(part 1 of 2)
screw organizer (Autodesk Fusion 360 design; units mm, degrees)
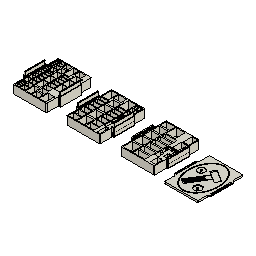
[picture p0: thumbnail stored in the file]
sketch "Sketch1" plane through (0, 0, 0) normal (0, 0, 1) x axis (1, 0, 0)
  line L1 (84.5, 75) -> (-100, 75)
  line L2 (84.5, -175) -> (84.5, 75)
  line L3 (-100, -175) -> (84.5, -175)
  line L4 (-100, 75) -> (-100, -175)
  line L5 (-112, -110) -> (-100, -110)
  line L6 (-112, 10) -> (-112, -110)
  line L7 (-100, 10) -> (-112, 10)
  line L8 (-100, -110) -> (-100, 10)
  line L9 (96.5, 10) -> (84.5, 10)
  line L10 (96.5, -110) -> (96.5, 10)
  line L11 (84.5, -110) -> (96.5, -110)
  line L12 (84.5, 10) -> (84.5, -110)
  line L13 (-103, 7) -> (-109, 7)
  line L14 (-103, -107) -> (-103, 7)
  line L15 (-109, -107) -> (-103, -107)
  line L16 (-109, 7) -> (-109, -107)
  line L17 (93.5, 7) -> (87.5, 7)
  line L18 (93.5, -107) -> (93.5, 7)
  line L19 (87.5, -107) -> (93.5, -107)
  line L20 (87.5, 7) -> (87.5, -107)
  point P6 (-100, -110)
  point P10 (84.5, 10)
  point P2 (-100, 75)
  point P3 (84.5, 75)
  point P5 (-100, -175)
  point P1 (0, 0)
  point P7 (-112, -110)
  point P9 (-100, 10)
  point P11 (96.5, 10)
  point P13 (84.5, -110)
  point P4 (84.5, -175)
  horizontal L1
  vertical L2
  horizontal L3
  vertical L4
  horizontal L5
  vertical L6
  horizontal L7
  vertical L8
  coincident L4 P6
  horizontal L9
  vertical L10
  horizontal L11
  vertical L12
  coincident L2 P10
  dimension "d1" distance P2 P3 = 184.5 (= "210 mm - 25.5 mm")
  dimension "d2" distance P2 P5 = 250
  dimension "d219" distance P1 L4 = 100
  dimension "d220" distance P1 L1 = 75
  dimension "d229" distance P6 P7 = 12
  dimension "d230" distance P6 P9 = 120
  dimension "d231" distance P2 L7 = 65 (= "d232")
  dimension "d232" distance P5 L5 = 65
  dimension "d233" distance P10 P11 = 12
  dimension "d234" distance P10 P13 = 120
  dimension "d235" distance P4 L11 = 65 (= "d236")
  dimension "d236" distance P3 L9 = 65
  dimension "d237" = 3
  dimension "d238" = 3
extrude "Extrude1" new body sketch "Sketch1" profile of L1 L2 L3 L4 L8 L12 along normal blind 5
sketch "Sketch2" plane through (0, 0, 5) normal (0, 0, 1) x axis (-1, 0, 0)
  line L1 (-84.5, 175) -> (100, 175)
  line L2 (-84.5, -75) -> (-84.5, 175)
  line L3 (100, -75) -> (-84.5, -75)
  line L4 (100, 175) -> (100, -75)
  line L5 (79.6, -70) -> (95, -70)
  line L6 (79.6, -65) -> (79.6, -70)
  line L7 (95, -65) -> (79.6, -65)
  line L8 (95, -70) -> (95, -65)
  line L9 (74.6, -70) -> (79.6, -70)
  line L10 (74.6, -18.3867) -> (74.6, -70)
  line L11 (79.6, -18.3867) -> (74.6, -18.3867)
  line L12 (79.6, -70) -> (79.6, -18.3867)
  line L13 (79.6, -65) -> (95, -65)
  line L14 (79.6, -62.3467) -> (79.6, -65)
  line L15 (95, -62.3467) -> (79.6, -62.3467)
  line L16 (95, -65) -> (95, -62.3467)
  curve K1
  curve K2
  curve K3
  curve K4
  curve K5
  curve K6
  curve K7
  curve K8
  line L17 (79.6, -62.3467) -> (95, -62.3467)
  line L18 (79.6, -56.3467) -> (79.6, -62.3467)
  line L19 (95, -56.3467) -> (79.6, -56.3467)
  line L20 (95, -62.3467) -> (95, -56.3467)
  line L21 (79.6, -56.3467) -> (95, -56.3467)
  line L22 (79.6, -53.6933) -> (79.6, -56.3467)
  line L23 (95, -53.6933) -> (79.6, -53.6933)
  line L24 (95, -56.3467) -> (95, -53.6933)
  curve K9
  curve K10
  curve K11
  curve K12
  line L25 (79.6, -53.6933) -> (95, -53.6933)
  line L26 (79.6, -46.6933) -> (79.6, -53.6933)
  line L27 (95, -46.6933) -> (79.6, -46.6933)
  line L28 (95, -53.6933) -> (95, -46.6933)
  line L29 (95, -46.6933) -> (79.6, -46.6933)
  line L30 (95, -44.04) -> (95, -46.6933)
  line L31 (79.6, -44.04) -> (95, -44.04)
  line L32 (79.6, -46.6933) -> (79.6, -44.04)
  curve K13
  curve K14
  curve K15
  curve K16
  line L33 (79.6, -44.04) -> (95, -44.04)
  line L34 (79.6, -36.04) -> (79.6, -44.04)
  line L35 (95, -36.04) -> (79.6, -36.04)
  line L36 (95, -44.04) -> (95, -36.04)
  curve K17
  curve K18
  curve K19
  curve K20
  line L37 (95, -36.04) -> (79.6, -36.04)
  line L38 (95, -33.3867) -> (95, -36.04)
  line L39 (79.6, -33.3867) -> (95, -33.3867)
  line L40 (79.6, -36.04) -> (79.6, -33.3867)
  line L41 (79.6, -33.3867) -> (95, -33.3867)
  line L42 (79.6, -23.3867) -> (79.6, -33.3867)
  line L43 (95, -23.3867) -> (79.6, -23.3867)
  line L44 (95, -33.3867) -> (95, -23.3867)
  curve K21
  curve K22
  curve K23
  curve K24
  line L45 (79.6, -23.3867) -> (95, -23.3867)
  line L46 (79.6, -18.3867) -> (79.6, -23.3867)
  line L47 (95, -18.3867) -> (79.6, -18.3867)
  line L48 (95, -23.3867) -> (95, -18.3867)
  line L49 (75.6, -18.3867) -> (95, -18.3867)
  line L50 (75.6, -12.9867) -> (75.6, -18.3867)
  line L51 (95, -12.9867) -> (75.6, -12.9867)
  line L52 (95, -18.3867) -> (95, -12.9867)
  line L53 (70.6, -18.3867) -> (74.6, -18.3867)
  line L54 (70.6, -23.3867) -> (70.6, -18.3867)
  line L55 (74.6, -23.3867) -> (70.6, -23.3867)
  line L56 (74.6, -18.3867) -> (74.6, -23.3867)
  line L57 (70.6, -18.3867) -> (75.6, -18.3867)
  line L58 (70.6, 122.44) -> (70.6, -18.3867)
  line L59 (75.6, 122.44) -> (70.6, 122.44)
  line L60 (75.6, -18.3867) -> (75.6, 122.44)
  curve K25
  curve K26
  curve K27
  curve K28
  line L61 (95, -12.9867) -> (75.6, -12.9867)
  line L62 (95, -10.3333) -> (95, -12.9867)
  line L63 (75.6, -10.3333) -> (95, -10.3333)
  line L64 (75.6, -12.9867) -> (75.6, -10.3333)
  line L65 (75.6, -10.3333) -> (95, -10.3333)
  line L66 (75.6, -3.9333) -> (75.6, -10.3333)
  line L67 (95, -3.9333) -> (75.6, -3.9333)
  line L68 (95, -10.3333) -> (95, -3.9333)
  curve K29
  curve K30
  curve K31
  curve K32
  curve K33
  curve K34
  curve K35
  curve K36
  line L69 (95, -3.9333) -> (75.6, -3.9333)
  line L70 (95, -1.28) -> (95, -3.9333)
  line L71 (75.6, -1.28) -> (95, -1.28)
  line L72 (75.6, -3.9333) -> (75.6, -1.28)
  line L73 (75.6, -1.28) -> (95, -1.28)
  line L74 (75.6, 8.12) -> (75.6, -1.28)
  line L75 (95, 8.12) -> (75.6, 8.12)
  line L76 (95, -1.28) -> (95, 8.12)
  line L77 (95, 8.12) -> (75.6, 8.12)
  line L78 (95, 10.7733) -> (95, 8.12)
  line L79 (75.6, 10.7733) -> (95, 10.7733)
  line L80 (75.6, 8.12) -> (75.6, 10.7733)
  curve K37
  curve K38
  curve K39
  curve K40
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  point P15 (79.6, -62.3467)
  point P8 (79.6, -70)
  point P10 (95, -65)
  point P19 (95, -56.3467)
  point P24 (79.6, -46.6933)
  point P25 (95, -46.6933)
  point P30 (79.6, -36.04)
  point P31 (95, -36.04)
  point P36 (79.6, -23.3867)
  point P37 (95, -23.3867)
  point P39 (95, -18.3867)
  point P42 (95, -12.9867)
  point P54 (95, -3.9333)
  point P58 (75.6, 8.12)
  point P59 (95, 8.12)
  point P61 (95, 10.7733)
  point P67 (75.6, 23.8267)
  point P64 (95, 21.1733)
  point P70 (95, 36.2267)
  point P76 (75.6, 53.28)
  point P77 (95, 53.28)
  point P86 (75.6, 74.9867)
  point P84 (95, 72.3333)
  point P92 (75.6, 98.04)
  point P89 (95, 95.3867)
  point P95 (75.6, 122.44)
  point P96 (95, 122.44)
  point P97 (72.1, 122.44)
  point P99 (95, 127.44)
  point P105 (95, 134.34)
  point P111 (95, 144.8933)
  point P117 (95, 156.4467)
  point P123 (95, 170)
  point P122 (72.1, 170)
  point P124 (72.1, 170)
  point P127 (74.6, -57.1)
  point P136 (74.6, -40.2)
  point P138 (74.6, -38.2)
  point P148 (70.6, -17.3)
  point P147 (70.6, -19.3)
  point P152 (70.6, 5.6)
  point P62 (75.6, 10.7733)
  point P165 (70.6, 20)
  point P167 (70.6, 24.0286)
  point P171 (70.6, 35.4286)
  point P177 (70.6, 52.8571)
  point P183 (70.6, 72.2857)
  point P185 (70.6, 76.3143)
  point P189 (70.6, 93.7143)
  point P191 (70.6, 97.7429)
  point P195 (70.6, 117.1429)
  point P101 (67.1, 170)
  point P205 (67.1, 142.5714)
  point P217 (46.7, -44.6)
  point P125 (51.7, -70)
  point P141 (47.7, -38.2)
  point P226 (42.7, -9.8)
  point P232 (42.7, -6.4289)
  point P235 (37.7, 26.9711)
  point P250 (37.7, 67.3711)
  point P260 (37.7, 112.7711)
  point P203 (39.2, 121.1714)
  point P207 (34.2, 170)
  point P221 (13.8, -70)
  point P277 (9.8, -16.6)
  point P295 (4.8, 18.4045)
  point P300 (4.8, 37.8379)
  point P308 (4.8, 59.2713)
  point P314 (4.8, 82.7047)
  point P244 (9.8, -11.4289)
  point P283 (4.8, 0.9711)
  point P320 (4.8, 108.138)
  point P243 (4.8, -11.4289)
  point P324 (1.3, 135.5714)
  point P267 (1.3, 170)
  point P273 (-18.1, -70)
  point P333 (-23.1, -40.6)
  point P336 (-23.1, -38.6)
  point P285 (-35.6, -16.4289)
  point P153 (42.7, 5.6)
  point P155 (70.6, 10.6)
  point P359 (-35.6, 37.2)
  point P365 (-35.6, 83.6)
  point P326 (-39.1, 170)
  point P7 (95, -70)
  point P11 (74.6, -70)
  point P16 (95, -62.3467)
  point P22 (95, -53.6933)
  point P28 (79.6, -44.04)
  point P27 (95, -44.04)
  point P34 (79.6, -33.3867)
  point P33 (95, -33.3867)
  point P40 (75.6, -18.3867)
  point P43 (70.6, -18.3867)
  point P46 (70.6, -18.3867)
  point P41 (75.6, -12.9867)
  point P51 (75.6, -10.3333)
  point P50 (95, -10.3333)
  point P53 (75.6, -3.9333)
  point P56 (75.6, -1.28)
  point P55 (95, -1.28)
  point P65 (75.6, 21.1733)
  point P68 (95, 23.8267)
  point P44 (70.6, -23.3867)
  point P71 (75.6, 36.2267)
  point P74 (75.6, 38.88)
  point P73 (95, 38.88)
  point P80 (75.6, 55.9333)
  point P83 (75.6, 72.3333)
  point P87 (95, 74.9867)
  point P90 (75.6, 95.3867)
  point P93 (95, 98.04)
  point P100 (67.1, 122.44)
  point P104 (72.1, 134.34)
  point P108 (72.1, 136.9933)
  point P107 (95, 136.9933)
  point P110 (72.1, 144.8933)
  point P114 (72.1, 147.5467)
  point P113 (95, 147.5467)
  point P119 (95, 159.1)
  point P128 (46.7, -70)
  point P133 (74.6, -55.1)
  point P135 (51.7, -40.2)
  point P139 (51.7, -38.2)
  point P140 (70.6, -38.2)
  point P143 (70.6, -19.3)
  point P144 (42.7, -38.2)
  point P142 (47.7, -19.3)
  point P149 (47.7, -17.3)
  point P156 (42.7, -6.4289)
  point P157 (37.7, -6.4289)
  point P159 (42.7, -1.4289)
  point P160 (37.7, 5.6)
  point P164 (42.7, 20)
  point P168 (42.7, 24.0286)
  point P174 (70.6, 39.4571)
  point P180 (70.6, 56.8857)
  point P182 (42.7, 72.2857)
  point P186 (42.7, 76.3143)
  point P188 (42.7, 93.7143)
  point P192 (42.7, 97.7429)
  point P47 (70.6, 122.44)
  point P196 (67.1, 122.44)
  point P199 (67.1, 117.1429)
  point P202 (67.1, 121.1714)
  point P206 (34.2, 121.1714)
  point P211 (67.1, 146.6)
  point P214 (67.1, 170)
  point P215 (18.8, -70)
  point P218 (18.8, -44.6)
  point P224 (14.8, -38.2)
  point P227 (9.8, -38.2)
  point P233 (9.8, -6.4289)
  point P236 (13.8, -38.2)
  point P238 (9.8, -43.2)
  point P239 (4.8, -6.4289)
  point P242 (4.8, -6.4289)
  point P247 (37.7, 28.9711)
  point P253 (37.7, 69.3711)
  point P256 (37.7, 112.7711)
  point P259 (34.2, 116.1714)
  point P262 (6.3, 170)
  point P264 (34.2, 121.6)
  point P265 (6.3, 116.1714)
  point P266 (1.3, 116.1714)
  point P271 (1.3, 111.1714)
  point P272 (9.8, -70)
  point P276 (-18.1, -11.4289)
  point P278 (-23.1, -11.4289)
  point P281 (-30.6, -11.4289)
  point P284 (-35.6, -11.4289)
  point P286 (-23.1, -16.4289)
  point P287 (-35.6, -11.4289)
  point P292 (4.8, 4.0045)
  point P298 (4.8, 21.4379)
  point P297 (-30.6, 21.4379)
  point P301 (-30.6, 37.8379)
  point P304 (-30.6, 40.8713)
  point P303 (4.8, 40.8713)
  point P307 (4.8, 59.2713)
  point P306 (-30.6, 59.2713)
  point P310 (-30.6, 62.3047)
  point P309 (4.8, 62.3047)
  point P313 (4.8, 82.7047)
  point P312 (-30.6, 82.7047)
  point P316 (-30.6, 85.738)
  point P315 (4.8, 85.738)
  point P319 (4.8, 108.138)
  point P322 (-34.1, 111.1714)
  point P325 (-39.1, 111.1714)
  point P327 (-34.1, 170)
  point P330 (-34.1, 143.6)
  point P279 (-23.1, -70)
  point P331 (-58.5, -70)
  point P337 (-63.5, -70)
  point P340 (-35.6, -38.6)
  point P341 (-71, -38.6)
  point P343 (-35.6, -4.2)
  point P344 (-76, -38.6)
  point P349 (-39.1, 106.1714)
  point P342 (-71, -4.2)
  point P352 (-71, -2.2)
  point P353 (-63.5, -40.6)
  point P356 (-63.5, -43.6)
  point P351 (-35.6, -2.2)
  point P362 (-35.6, 39.2)
  point P368 (-35.6, 85.6)
  point P369 (-74.5, 170)
  point P371 (-39.1, 120.6)
  point P372 (-74.5, 85.6)
  point P373 (-79.5, 85.6)
  horizontal L5
  vertical L6
  horizontal L7
  vertical L8
  horizontal L9
  vertical L10
  horizontal L11
  vertical L12
  horizontal L13
  vertical L14
  horizontal L15
  vertical L16
  coincident L12 P15
  coincident P8
  coincident L3
  coincident P10
  coincident L4
  horizontal L17
  vertical L18
  horizontal L19
  vertical L20
  horizontal L21
  vertical L22
  horizontal L23
  vertical L24
  coincident P19
  coincident L4
  horizontal L25
  vertical L26
  horizontal L27
  vertical L28
  coincident L12 P24
  horizontal L29
  vertical L30
  horizontal L31
  vertical L32
  coincident L4
  coincident P25
  horizontal L33
  vertical L34
  horizontal L35
  vertical L36
  coincident L12 P30
  coincident L4
  coincident P31
  horizontal L37
  vertical L38
  horizontal L39
  vertical L40
  horizontal L41
  vertical L42
  horizontal L43
  vertical L44
  coincident L12 P36
  coincident P37
  coincident L4
  horizontal L45
  vertical L46
  horizontal L47
  vertical L48
  horizontal L49
  vertical L50
  horizontal L51
  vertical L52
  horizontal L53
  vertical L54
  horizontal L55
  vertical L56
  horizontal L57
  vertical L58
  horizontal L59
  vertical L60
  coincident P36
  coincident P39
  horizontal L61
  vertical L62
  horizontal L63
  vertical L64
  horizontal L65
  vertical L66
  coincident P42
  coincident L4
  coincident P54
  coincident L4
  collinear L60 L66
  horizontal L69
  vertical L70
  horizontal L71
  vertical L72
  horizontal L73
  vertical L74
  horizontal L75
  vertical L76
  coincident L60 P58
  horizontal L77
  vertical L78
  horizontal L79
  vertical L80
  coincident P59
  coincident L4
  coincident L4
  coincident P61
  coincident L60 P67
  coincident P64
  collinear L12 L22
  collinear L12 L18
  coincident L4
  coincident P70
  coincident L60 P76
  coincident L4
  coincident P77
  coincident L60 P86
  coincident L4
  coincident P84
  coincident L60 P92
  coincident L4
  coincident P89
  coincident L60 P95
  coincident L4
  coincident P96
  coincident P97
  coincident P99
  coincident L4
  coincident P105
  coincident L4
  coincident P111
  coincident L4
  coincident P117
  coincident L4
  coincident P123
  coincident P122 P124
  coincident P8
  coincident P127
  midpoint L22
  coincident P136
  coincident L10 P138
  coincident L58 P148
  coincident L34
  coincident P147
  coincident L50
  coincident P152
  coincident P62
  coincident P165
  coincident L58 P167
  coincident P171
  coincident L60
  coincident P177
  coincident L60
  coincident P183
  coincident L58 P185
  coincident P189
  coincident L58 P191
  coincident L60
  coincident P195
  coincident P101
  coincident P205
  collinear L71 K39
  collinear L63 K35
  collinear L47 K31
  collinear L39 K23
  collinear L33 K19
  collinear L23 K15
  collinear L17 K11
  coincident P217
  coincident P125
  coincident P141
  coincident P226
  coincident P232
  coincident P235
  coincident P250
  coincident P260
  coincident P203
  coincident P207
  coincident P221
  coincident P277
  coincident P295
  coincident P300
  coincident P308
  coincident P314
  coincident P244
  coincident P283
  coincident P320
  coincident P243
  coincident P324
  coincident P267
  coincident P273
  coincident P333
  coincident P336
  coincident P285
  coincident P153
  coincident P155
  coincident P359
  coincident P365
  coincident P326
  dimension "d5" = -5
  dimension "d6" distance P7 P8 = 15.4 (= "( 3 * 5 ) * 1 mm + 0.4 mm")
  dimension "d7" distance P7 P10 = 5 (= "1.6 mm + 0.4 mm + 3 mm")
  dimension "d8" distance P8 P11 = 5
  dimension "d10" distance P10 P16 = 2.6533 (= "d73")
  dimension "d13" distance P16 P19 = 6
  dimension "d14" distance P19 P22 = 2.6533 (= "d10")
  dimension "d16" distance P22 P25 = 7
  dimension "d17" distance P24 P28 = 2.6533 (= "d14")
  dimension "d19" distance P27 P31 = 8
  dimension "d21" distance P30 P34 = 2.6533 (= "d17")
  dimension "d22" distance P33 P37 = 10
  dimension "d24" distance P39 P40 = 19.4 (= "( 3.8 * 5 ) * 1 mm + 0.4 mm")
  dimension "d25" distance P39 P42 = 5.4 (= "5 mm + 0.4 mm")
  dimension "d26" distance L50 P43 = 5
  dimension "d27" distance P40 P46 = 5 (= "d8")
  dimension "d30" distance P41 P51 = 2.6533 (= "d21")
  dimension "d31" distance P50 P54 = 6.4
  dimension "d34" distance P53 P56 = 2.6533 (= "d30")
  dimension "d35" distance P55 P59 = 9.4
  dimension "d36" distance P58 P62 = 2.6533 (= "d34")
  dimension "d38" distance P62 P65 = 10.4
  dimension "d40" distance P64 P68 = 2.6533 (= "d36")
  dimension "d41" distance P43 P44 = 5 (= "d26")
  dimension "d42" distance P67 P71 = 12.4
  dimension "d44" distance P71 P74 = 2.6533 (= "d40")
  dimension "d45" distance P73 P77 = 14.4
  dimension "d47" distance P76 P80 = 2.6533 (= "d44")
  dimension "d48" distance P80 P83 = 16.4
  dimension "d49" distance P84 P87 = 2.6533 (= "d47")
  dimension "d51" distance P86 P90 = 20.4
  dimension "d52" distance P89 P93 = 2.6533 (= "d49")
  dimension "d54" distance P93 P96 = 24.4
  dimension "d56" distance P96 P97 = 22.9 (= "( 4.5 * 5 ) * 1 mm + 0.4 mm")
  dimension "d57" distance P96 P99 = 5
  dimension "d58" distance P97 P100 = 5
  dimension "d60" distance P99 P105 = 6.9
  dimension "d61" distance P104 P108 = 2.6533 (= "d52")
  dimension "d62" distance P107 P111 = 7.9
  dimension "d65" distance P110 P114 = 2.6533 (= "d61")
  dimension "d66" distance P113 P117 = 8.9
  dimension "d69" distance P119 P123 = 10.9
  dimension "d71" distance L47 K27 = 5
  dimension "d73" distance = 2.6533
  dimension "d74" distance P11 P125 = 22.9
  dimension "d75" distance P11 P127 = 12.9
  dimension "d76" distance P125 P128 = 5
  dimension "d77" distance P127 P133 = 2
  dimension "d79" distance P133 P136 = 14.9
  dimension "d81" distance P135 P139 = 2
  dimension "d82" distance P140 P141 = 22.9
  dimension "d83" distance P140 P143 = 18.9
  dimension "d84" distance P141 P144 = 5
  dimension "d85" distance P142 P149 = 2
  dimension "d86" distance P148 P152 = 22.9
  dimension "d89" distance P152 P153 = 27.9 (= "( 5.5 * 5 ) * 1 mm + 0.4 mm")
  dimension "d90" distance P152 P155 = 5
  dimension "d91" distance P156 P157 = 5
  dimension "d92" distance P156 P159 = 5
  dimension "d93" distance P153 P160 = 5
  dimension "d95" distance P155 P165 = 9.4
  dimension "d97" distance P164 P168 = 4.0286 (= "d100")
  dimension "d98" distance P167 P171 = 11.4
  dimension "d100" distance P171 P174 = 4.0286 (= "d103")
  dimension "d101" distance P174 P177 = 13.4
  dimension "d103" distance P177 P180 = 4.0286 (= "d106")
  dimension "d104" distance P180 P183 = 15.4
  dimension "d106" distance P182 P186 = 4.0286 (= "d109")
  dimension "d107" distance P185 P189 = 17.4
  dimension "d109" distance P188 P192 = 4.0286 (= "d114")
  dimension "d110" distance P191 P195 = 19.4
  dimension "d112" distance P47 P196 = 3.5
  dimension "d114" distance P199 P202 = 4.0286 (= "d120")
  dimension "d115" distance P202 P203 = 27.9
  dimension "d116" distance P202 P205 = 21.4
  dimension "d117" distance P203 P206 = 5
  dimension "d119" distance P211 P214 = 23.4
  dimension "d120" distance = 4.0286
  dimension "d123" distance P128 P215 = 27.9
  dimension "d124" distance P128 P217 = 25.4
  dimension "d125" distance P217 P218 = 27.9
  dimension "d126" distance P215 P221 = 5
  dimension "d128" distance P144 P224 = 27.9
  dimension "d129" distance P144 P226 = 28.4
  dimension "d130" distance P224 P227 = 5
  dimension "d132" distance = 6.4
  dimension "d134" distance P157 P233 = 27.9
  dimension "d135" distance P157 P235 = 33.4
  dimension "d136" distance P227 P236 = 4
  dimension "d137" distance P227 P238 = 5
  dimension "d138" distance P233 P239 = 5
  dimension "d139" distance P233 P242 = 5
  dimension "d140" distance P233 P244 = 5
  dimension "d142" distance P235 P247 = 2
  dimension "d154" distance P247 P250 = 38.4
  dimension "d155" distance P250 P253 = 2
  dimension "d156" distance P253 P256 = 43.4
  dimension "d157" distance P206 P259 = 5
  dimension "d158" distance = 3.3711
  dimension "d159" distance P207 P262 = 27.9
  dimension "d160" distance P207 P264 = 48.4
  dimension "d161" distance P265 P266 = 5
  dimension "d162" distance P266 P271 = 5
  dimension "d166" distance P272 P273 = 27.9
  dimension "d167" distance = 53.4
  dimension "d168" distance P276 P278 = 5
  dimension "d171" distance P243 P281 = 35.4 (= "( 7 * 5 ) * 1 mm + 0.4 mm")
  dimension "d172" distance P243 P283 = 12.4
  dimension "d173" distance P278 P284 = 12.5
  dimension "d174" distance P278 P286 = 5
  dimension "d175" distance P281 P287 = 5
  dimension "d176" distance P283 P292 = 3.0334 (= "d178")
  dimension "d177" distance P292 P295 = 14.4
  dimension "d178" distance P295 P298 = 3.0334 (= "d180")
  dimension "d179" distance P297 P301 = 16.4
  dimension "d180" distance P301 P304 = 3.0334 (= "d182")
  dimension "d181" distance P303 P307 = 18.4
  dimension "d182" distance P306 P310 = 3.0334 (= "d184")
  dimension "d183" distance P309 P313 = 20.4
  dimension "d184" distance P312 P316 = 3.0334 (= "d186")
  dimension "d185" distance P315 P319 = 22.4
  dimension "d186" distance = 3.0334
  dimension "d194" distance P271 P322 = 35.4
  dimension "d195" distance P271 P324 = 24.4
  dimension "d196" distance P322 P325 = 5
  dimension "d197" distance P327 P330 = 26.4
  dimension "d200" distance P279 P331 = 35.4
  dimension "d201" distance P279 P333 = 29.4
  dimension "d202" distance P333 P336 = 2
  dimension "d203" distance P331 P337 = 5
  dimension "d204" distance P340 P341 = 35.4
  dimension "d205" distance P340 P343 = 34.4
  dimension "d206" distance P341 P344 = 5
  dimension "d207" distance P325 P349 = 5
  dimension "d208" distance P342 P352 = 2
  dimension "d211" distance P353 P356 = 3
  dimension "d212" distance P351 P359 = 39.4
  dimension "d213" distance P359 P362 = 2
  dimension "d214" distance P362 P365 = 44.4
  dimension "d215" distance P365 P368 = 2
  dimension "d216" distance P326 P369 = 35.4
  dimension "d217" distance P326 P371 = 49.4
  dimension "d218" distance P372 P373 = 5
  dimension "d11" Text1-Height = 4
  dimension "d12" Text2-Height = 4
  dimension "d15" Text3-Height = 4
  dimension "d18" Text4-Height = 4
  dimension "d20" Text5-Height = 4
  dimension "d23" Text6-Height = 4
  dimension "d29" Text7-Height = 4
  dimension "d32" Text8-Height = 4
  dimension "d33" Text9-Height = 4
  dimension "d37" Text10-Height = 4
  dimension "d39" Text11-Height = 4
  dimension "d43" Text12-Height = 4
  dimension "d46" Text13-Height = 3.5
  dimension "d50" Text14-Height = 3.5
  dimension "d53" Text15-Height = 3.5
  dimension "d55" Text16-Height = 3
  dimension "d59" Text17-Height = 4
  dimension "d63" Text18-Height = 4
  dimension "d64" Text19-Height = 4
  dimension "d67" Text20-Height = 4
  dimension "d70" Text21-Height = 4
  dimension "d78" Text22-Height = 3.5
  dimension "d80" Text23-Height = 3.5
  dimension "d87" Text24-Height = 4
  dimension "d88" Text25-Height = 3
  dimension "d96" Text27-Height = 4
  dimension "d99" Text28-Height = 4
  dimension "d102" Text29-Height = 3.5
  dimension "d105" Text30-Height = 3.5
  dimension "d108" Text31-Height = 3.5
  dimension "d111" Text32-Height = 3.5
  dimension "d121" Text33-Height = 3
  dimension "d122" Text34-Height = 3
  dimension "d127" Text35-Height = 3
  dimension "d131" Text36-Height = 3
  dimension "d141" Text37-Height = 3
  dimension "d163" Text38-Height = 3
  dimension "d164" Text39-Height = 3
  dimension "d165" Text40-Height = 3
  dimension "d169" Text41-Height = 3
  dimension "d187" Text43-Height = 3.5
  dimension "d188" Text44-Height = 3.5
  dimension "d189" Text45-Height = 3.5
  dimension "d190" Text46-Height = 3.5
  dimension "d191" Text47-Height = 4
  dimension "d192" Text48-Height = 3.5
  dimension "d193" Text48-Height = 3.5
  dimension "d198" Text49-Height = 3
  dimension "d199" Text50-Height = 3
  dimension "d209" Text51-Height = 3
  dimension "d210" Text52-Height = 4
  dimension "d223" Text52-Height = 4
  dimension "d224" Text53-Height = 3
  dimension "d225" Text54-Height = 3
  dimension "d226" Text55-Height = 3
sketch "Sketch3" plane through (0, 0, 0) normal (0, 0, 1) x axis (1, 0, 0)
  line L1 (81.4, 200) -> (50, 200)
  line L2 (81.4, 252.9) -> (81.4, 200)
  line L3 (50, 252.9) -> (81.4, 252.9)
  line L4 (50, 200) -> (50, 252.9)
  line L5 (76.4, 205) -> (55, 205)
  line L6 (76.4, 247.9) -> (76.4, 205)
  line L7 (55, 247.9) -> (76.4, 247.9)
  line L8 (55, 205) -> (55, 247.9)
  point P2 (50, 200)
  point P3 (81.4, 200)
  point P5 (50, 252.9)
  point P6 (55, 205)
  point P7 (76.4, 205)
  point P9 (55, 247.9)
  horizontal L1
  vertical L2
  horizontal L3
  vertical L4
  horizontal L5
  vertical L6
  horizontal L7
  vertical L8
  dimension "d143" distance P2 P3 = 31.4 (= "21.4 mm + 10 mm")
  dimension "d144" distance P2 P5 = 52.9 (= "( 8.5 * 5 ) * 1 mm + 0.4 mm + 10 mm")
  dimension "d145" distance P6 P7 = 21.4
  dimension "d146" distance P6 P9 = 42.9
  dimension "d147" distance L1 L5 = 5
  dimension "d148" distance L4 L8 = 5
  dimension "d149" distance L2 L6 = 5
extrude "Extrude2" new body sketch "Sketch3" against normal blind 5
extrude "Extrude3" add sketch "Sketch3" along normal blind 10
extrude "Extrude4" add sketch "Sketch2" along normal blind 40
extrude "Extrude5" cut sketch "Sketch2" along normal blind 44
extrude "Extrude6" add sketch "Sketch1" profile of L2 L4 L5 L6 L7 L8 L9 L10 L11 L12 L16 L13 L15 L14 L20 L17 L18 L19 along normal blind 50
extrude "Extrude7" add sketch "Sketch1" profile of L16 L13 L15 L14 L20 L17 L18 L19 along normal blind 70
fillet "Fillet1" radius 3
extrude "Extrude8" add sketch "Sketch2" along normal blind 38
fillet "Fillet2" radius 3
sketch "Sketch4" plane through (0, 0, 0) normal (0, 0, 1) x axis (1, 0, 0)
  line L1 (382.7937, 73.3642) -> (198.2937, 73.3642)
  line L2 (382.7937, -176.6358) -> (382.7937, 73.3642)
  line L3 (198.2937, -176.6358) -> (382.7937, -176.6358)
  line L4 (198.2937, 73.3642) -> (198.2937, -176.6358)
  point P2 (198.2937, 73.3642)
  point P3 (382.7937, 73.3642)
  point P5 (198.2937, -176.6358)
  horizontal L1
  vertical L2
  horizontal L3
  vertical L4
  dimension "d249" distance P2 P3 = 184.5
  dimension "d250" distance P2 P5 = 250
extrude "Extrude9" new body sketch "Sketch4" along normal blind 5
sketch "Sketch5" plane through (0, 0, 5) normal (0, 0, 1) x axis (-1, 0, 0)
  line L1 (-382.7937, 176.6358) -> (-198.2937, 176.6358)
  line L2 (-382.7937, -73.3642) -> (-382.7937, 176.6358)
  line L3 (-198.2937, -73.3642) -> (-382.7937, -73.3642)
  line L4 (-198.2937, 176.6358) -> (-198.2937, -73.3642)
  line L5 (-377.7937, -68.3642) -> (-377.7937, 171.6358)
  line L6 (-203.2937, -68.3642) -> (-377.7937, -68.3642)
  line L7 (-203.2937, 171.6358) -> (-203.2937, -68.3642)
  line L8 (-377.7937, 171.6358) -> (-203.2937, 171.6358)
  line L9 (-238.6937, -68.3642) -> (-203.2937, -68.3642)
  line L10 (-238.6937, -13.9642) -> (-238.6937, -68.3642)
  line L11 (-203.2937, -13.9642) -> (-238.6937, -13.9642)
  line L12 (-203.2937, -68.3642) -> (-203.2937, -13.9642)
  line L13 (-243.6937, -68.3642) -> (-238.6937, -68.3642)
  line L14 (-243.6937, -13.9642) -> (-243.6937, -68.3642)
  line L15 (-238.6937, -13.9642) -> (-243.6937, -13.9642)
  line L16 (-238.6937, -68.3642) -> (-238.6937, -13.9642)
  line L17 (-246.1937, -13.9642) -> (-203.2937, -13.9642)
  line L18 (-246.1937, -8.9642) -> (-246.1937, -13.9642)
  line L19 (-203.2937, -8.9642) -> (-246.1937, -8.9642)
  line L20 (-203.2937, -13.9642) -> (-203.2937, -8.9642)
  curve K1
  curve K2
  curve K3
  curve K4
  curve K5
  curve K6
  curve K7
  curve K8
  curve K9
  curve K10
  curve K11
  curve K12
  line L21 (-251.1937, -13.9642) -> (-246.1937, -13.9642)
  line L22 (-251.1937, 171.6358) -> (-251.1937, -13.9642)
  line L23 (-246.1937, 171.6358) -> (-251.1937, 171.6358)
  line L24 (-246.1937, -13.9642) -> (-246.1937, 171.6358)
  line L25 (-251.1937, -13.9642) -> (-243.6937, -13.9642)
  line L26 (-251.1937, -18.9642) -> (-251.1937, -13.9642)
  line L27 (-243.6937, -18.9642) -> (-251.1937, -18.9642)
  line L28 (-243.6937, -13.9642) -> (-243.6937, -18.9642)
  line L29 (-246.1937, -8.9642) -> (-203.2937, -8.9642)
  line L30 (-246.1937, 6.4358) -> (-246.1937, -8.9642)
  line L31 (-203.2937, 6.4358) -> (-246.1937, 6.4358)
  line L32 (-203.2937, -8.9642) -> (-203.2937, 6.4358)
  line L33 (-246.1937, 6.4358) -> (-203.2937, 6.4358)
  line L34 (-246.1937, 11.5691) -> (-246.1937, 6.4358)
  line L35 (-203.2937, 11.5691) -> (-246.1937, 11.5691)
  line L36 (-203.2937, 6.4358) -> (-203.2937, 11.5691)
  line L37 (-246.1937, 11.5691) -> (-203.2937, 11.5691)
  line L38 (-246.1937, 28.9691) -> (-246.1937, 11.5691)
  line L39 (-203.2937, 28.9691) -> (-246.1937, 28.9691)
  line L40 (-203.2937, 11.5691) -> (-203.2937, 28.9691)
  line L41 (-246.1937, 28.9691) -> (-203.2937, 28.9691)
  line L42 (-246.1937, 34.1024) -> (-246.1937, 28.9691)
  line L43 (-203.2937, 34.1024) -> (-246.1937, 34.1024)
  line L44 (-203.2937, 28.9691) -> (-203.2937, 34.1024)
  line L45 (-246.1937, 34.1024) -> (-203.2937, 34.1024)
  line L46 (-246.1937, 53.5024) -> (-246.1937, 34.1024)
  line L47 (-203.2937, 53.5024) -> (-246.1937, 53.5024)
  line L48 (-203.2937, 34.1024) -> (-203.2937, 53.5024)
  line L49 (-246.1937, 53.5024) -> (-203.2937, 53.5024)
  line L50 (-246.1937, 58.6358) -> (-246.1937, 53.5024)
  line L51 (-203.2937, 58.6358) -> (-246.1937, 58.6358)
  line L52 (-203.2937, 53.5024) -> (-203.2937, 58.6358)
  line L53 (-246.1937, 58.6358) -> (-203.2937, 58.6358)
  line L54 (-246.1937, 80.0358) -> (-246.1937, 58.6358)
  line L55 (-203.2937, 80.0358) -> (-246.1937, 80.0358)
  line L56 (-203.2937, 58.6358) -> (-203.2937, 80.0358)
  line L57 (-246.1937, 80.0358) -> (-203.2937, 80.0358)
  line L58 (-246.1937, 85.1691) -> (-246.1937, 80.0358)
  line L59 (-203.2937, 85.1691) -> (-246.1937, 85.1691)
  line L60 (-203.2937, 80.0358) -> (-203.2937, 85.1691)
  line L61 (-246.1937, 85.1691) -> (-203.2937, 85.1691)
  line L62 (-246.1937, 108.5691) -> (-246.1937, 85.1691)
  line L63 (-203.2937, 108.5691) -> (-246.1937, 108.5691)
  line L64 (-203.2937, 85.1691) -> (-203.2937, 108.5691)
  line L65 (-246.1937, 108.5691) -> (-203.2937, 108.5691)
  line L66 (-246.1937, 113.7024) -> (-246.1937, 108.5691)
  line L67 (-203.2937, 113.7024) -> (-246.1937, 113.7024)
  line L68 (-203.2937, 108.5691) -> (-203.2937, 113.7024)
  line L69 (-246.1937, 113.7024) -> (-203.2937, 113.7024)
  line L70 (-246.1937, 139.1024) -> (-246.1937, 113.7024)
  line L71 (-203.2937, 139.1024) -> (-246.1937, 139.1024)
  line L72 (-203.2937, 113.7024) -> (-203.2937, 139.1024)
  line L73 (-246.1937, 171.6358) -> (-203.2937, 171.6358)
  line L74 (-246.1937, 144.2358) -> (-246.1937, 171.6358)
  line L75 (-203.2937, 144.2358) -> (-246.1937, 144.2358)
  line L76 (-203.2937, 171.6358) -> (-203.2937, 144.2358)
  curve K13
  curve K14
  curve K15
  curve K16
  curve K17
  curve K18
  curve K19
  curve K20
  curve K21
  curve K22
  curve K23
  curve K24
  curve K25
  curve K26
  curve K27
  curve K28
  curve K29
  curve K30
  curve K31
  curve K32
  curve K33
  curve K34
  curve K35
  curve K36
  curve K37
  curve K38
  curve K39
  curve K40
  line L77 (-286.5937, -68.3642) -> (-243.6937, -68.3642)
  line L78 (-286.5937, -37.9642) -> (-286.5937, -68.3642)
  line L79 (-243.6937, -37.9642) -> (-286.5937, -37.9642)
  line L80 (-243.6937, -68.3642) -> (-243.6937, -37.9642)
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  point P10 (-238.6937, -68.3642)
  point P12 (-203.2937, -13.9642)
  point P16 (-246.1937, -13.9642)
  point P18 (-203.2937, -8.9642)
  point P20 (-251.1937, 171.6358)
  point P26 (-246.1937, 6.4358)
  point P29 (-246.1937, 11.5691)
  point P32 (-246.1937, 28.9691)
  point P35 (-246.1937, 34.1024)
  point P38 (-246.1937, 53.5024)
  point P41 (-246.1937, 58.6358)
  point P44 (-246.1937, 80.0358)
  point P47 (-246.1937, 85.1691)
  point P50 (-246.1937, 108.5691)
  point P53 (-246.1937, 113.7024)
  point P56 (-246.1937, 139.1024)
  point P59 (-246.1937, 144.2358)
  point P27 (-203.2937, 6.4358)
  point P33 (-203.2937, 28.9691)
  point P39 (-203.2937, 53.5024)
  point P45 (-203.2937, 80.0358)
  point P51 (-203.2937, 108.5691)
  point P57 (-203.2937, 139.1024)
  point P9 (-203.2937, 171.6358)
  point P95 (-299.0937, -68.3642)
  point P106 (-344.4937, 171.6358)
  point P102 (-349.4937, -12.9642)
  point P104 (-299.0937, -7.9642)
  point P63 (-243.6937, -37.9642)
  point P73 (-251.1937, 6.9358)
  point P85 (-251.1937, 56.8358)
  point P91 (-251.1937, 111.7358)
  point P67 (-291.5937, -68.3642)
  point P98 (-299.0937, -12.9642)
  point P110 (-299.0937, 8.4358)
  point P116 (-299.0937, 30.6358)
  point P122 (-299.0937, 54.8358)
  point P128 (-299.0937, 81.0358)
  point P134 (-299.0937, 109.2358)
  point P140 (-299.0937, 139.4358)
  point P75 (-299.0937, 171.6358)
  point P144 (-198.2937, 111.6358)
  point P148 (-382.7937, 111.6358)
  point P176 (-377.7937, 22.4358)
  point P179 (-377.7937, -17.9642)
  point P99 (-346.9937, -68.3642)
  point P163 (-363.3937, -68.3642)
  point P164 (-363.3937, -46.9642)
  point P171 (-346.9937, -42.3642)
  point P195 (-377.7937, 50.0358)
  point P174 (-349.4937, 17.4358)
  point P181 (-354.8937, 22.4358)
  point P184 (-359.4437, 22.4358)
  point P175 (-377.7937, 17.4358)
  point P188 (-370.3937, 22.4358)
  point P187 (-359.4437, 40.8358)
  point P191 (-349.4937, 47.0358)
  point P190 (-377.7937, 43.8358)
  point P196 (-367.3937, 50.0358)
  point P199 (-349.4937, 80.6358)
  point P204 (-361.3937, 123.2358)
  point P206 (-377.7937, -40.9142)
  point P8 (-203.2937, -68.3642)
  point P13 (-243.6937, -68.3642)
  point P15 (-238.6937, -13.9642)
  point P19 (-251.1937, -13.9642)
  point P14 (-243.6937, -13.9642)
  point P24 (-243.6937, -18.9642)
  point P30 (-203.2937, 11.5691)
  point P36 (-203.2937, 34.1024)
  point P42 (-203.2937, 58.6358)
  point P48 (-203.2937, 85.1691)
  point P54 (-203.2937, 113.7024)
  point P60 (-203.2937, 144.2358)
  point P61 (-286.5937, -68.3642)
  point P66 (-243.6937, -28.4642)
  point P69 (-286.5937, -35.9642)
  point P70 (-251.1937, -28.4642)
  point P71 (-294.0937, -28.4642)
  point P74 (-299.0937, -28.4642)
  point P79 (-299.0937, -33.4642)
  point P82 (-251.1937, 16.4358)
  point P88 (-251.1937, 66.3358)
  point P94 (-251.1937, 121.2358)
  point P96 (-341.9937, -68.3642)
  point P101 (-341.9937, -12.9642)
  point P105 (-344.4937, -12.9642)
  point P113 (-299.0937, 12.2358)
  point P119 (-299.0937, 34.4358)
  point P125 (-299.0937, 58.6358)
  point P131 (-299.0937, 84.8358)
  point P137 (-299.0937, 113.0358)
  point P143 (-299.0937, 143.2358)
  point P145 (-186.2937, 111.6358)
  point P147 (-198.2937, -8.3642)
  point P149 (-394.7937, 111.6358)
  point P151 (-382.7937, -8.3642)
  point P160 (-357.3937, -68.3642)
  point P162 (-346.9937, -52.9642)
  point P7 (-377.7937, -68.3642)
  point P165 (-377.7937, -46.9642)
  point P168 (-349.4937, -17.9642)
  point P167 (-346.9937, -17.9642)
  point P169 (-363.3937, -17.9642)
  point P172 (-369.8937, -12.9642)
  point P177 (-349.4937, 22.4358)
  point P180 (-349.4937, -17.9642)
  point P183 (-349.4937, 37.8358)
  point P185 (-365.8437, 22.4358)
  point P192 (-358.8937, 47.0358)
  point P194 (-349.4937, 74.4358)
  point P198 (-377.7937, 80.4358)
  point P200 (-361.8937, 80.6358)
  point P202 (-349.4937, 117.0358)
  point P6 (-377.7937, 171.6358)
  point P203 (-361.3937, 171.6358)
  point P205 (-377.7937, 123.2358)
  point P207 (-366.3937, -40.9142)
  point P209 (-377.7937, -24.0142)
  horizontal L9
  vertical L10
  horizontal L11
  vertical L12
  horizontal L13
  vertical L14
  horizontal L15
  vertical L16
  horizontal L17
  vertical L18
  horizontal L19
  vertical L20
  coincident P10
  coincident L3
  coincident L4
  coincident P12
  coincident P16
  coincident P18
  horizontal L21
  vertical L22
  horizontal L23
  vertical L24
  coincident L8 P20
  horizontal L25
  vertical L26
  horizontal L27
  vertical L28
  collinear L22 L26
  horizontal L29
  vertical L30
  horizontal L31
  vertical L32
  coincident L24 P26
  horizontal L33
  vertical L34
  horizontal L35
  vertical L36
  coincident L30 P29
  horizontal L37
  vertical L38
  horizontal L39
  vertical L40
  coincident L24 P32
  horizontal L41
  vertical L42
  horizontal L43
  vertical L44
  coincident L24 P35
  horizontal L45
  vertical L46
  horizontal L47
  vertical L48
  coincident L24 P38
  horizontal L49
  vertical L50
  horizontal L51
  vertical L52
  coincident L24 P41
  horizontal L53
  vertical L54
  horizontal L55
  vertical L56
  coincident L24 P44
  horizontal L57
  vertical L58
  horizontal L59
  vertical L60
  coincident L24 P47
  horizontal L61
  vertical L62
  horizontal L63
  vertical L64
  coincident L24 P50
  horizontal L65
  vertical L66
  horizontal L67
  vertical L68
  coincident L24 P53
  horizontal L69
  vertical L70
  horizontal L71
  vertical L72
  coincident L24 P56
  horizontal L73
  vertical L74
  horizontal L75
  vertical L76
  coincident L24 P59
  coincident L4
  coincident P27
  coincident L4
  coincident P33
  coincident L4
  coincident P39
  coincident L4
  coincident P45
  coincident L4
  coincident P51
  coincident L4
  coincident P57
  coincident L4
  coincident P9
  horizontal L77
  vertical L78
  horizontal L79
  vertical L80
  coincident L6 P95
  coincident L8 P106
  coincident P102
  coincident P104
  coincident P10
  coincident P63
  coincident P73
  coincident L38
  coincident P85
  coincident L54
  coincident P91
  coincident L24
  coincident P20
  coincident P67
  coincident P98
  coincident P110
  coincident P116
  coincident P122
  coincident P128
  coincident P134
  coincident P140
  coincident P75
  coincident L4 P144
  coincident K36 P144
  coincident L2 P148
  coincident L5 P176
  coincident L5 P179
  coincident L3
  coincident P99
  coincident L3
  coincident P163
  coincident P164
  coincident P171
  coincident P102
  coincident L5 P195
  coincident P174
  coincident P181
  coincident P184
  coincident P175
  coincident P188
  coincident P187
  coincident P191
  coincident P190
  coincident P196
  coincident P199
  coincident L5
  coincident P204
  coincident L5 P206
  coincident P206
  dimension "d253" = -5
  dimension "d254" distance P8 P10 = 35.4
  dimension "d255" distance P8 P12 = 54.4
  dimension "d256" distance P10 P13 = 5
  dimension "d257" distance P10 P15 = 54.4
  dimension "d258" distance P12 P16 = 42.9 (= "( 8.5 * 5 ) * 1 mm + 0.4 mm")
  dimension "d259" distance P12 P18 = 5
  dimension "d263" distance P16 P19 = 5
  dimension "d264" distance P14 P24 = 5
  dimension "d265" distance P18 P27 = 15.4
  dimension "d266" distance P27 P30 = 5.1333 (= "d268")
  dimension "d267" distance P30 P33 = 17.4
  dimension "d268" distance P33 P36 = 5.1333 (= "d270")
  dimension "d269" distance P36 P39 = 19.4
  dimension "d270" distance P39 P42 = 5.1333 (= "d272")
  dimension "d271" distance P42 P45 = 21.4
  dimension "d272" distance P45 P48 = 5.1333 (= "d274")
  dimension "d273" distance P48 P51 = 23.4
  dimension "d274" distance P51 P54 = 5.1333 (= "d277")
  dimension "d275" distance P54 P57 = 25.4
  dimension "d276" distance P9 P60 = 27.4
  dimension "d277" distance L71 L75 = 5.1333
  dimension "d285" distance P13 P61 = 42.9
  dimension "d286" distance P13 P63 = 30.4
  dimension "d287" distance P63 P66 = 9.5 (= "d294")
  dimension "d288" distance P61 P67 = 5
  dimension "d289" distance P61 P69 = 32.4
  dimension "d290" distance P70 P71 = 42.9
  dimension "d291" distance P70 P73 = 35.4
  dimension "d292" distance P71 P74 = 5
  dimension "d293" distance P74 P79 = 5
  dimension "d294" distance P73 P82 = 9.5 (= "d296")
  dimension "d295" distance P82 P85 = 40.4
  dimension "d296" distance P85 P88 = 9.5 (= "d299")
  dimension "d297" distance P88 P91 = 45.4
  dimension "d298" distance P20 P94 = 50.4
  dimension "d299" distance = 9.5
  dimension "d300" distance P95 P96 = 42.9
  dimension "d301" distance P95 P98 = 55.4
  dimension "d302" distance P96 P99 = 5
  dimension "d303" distance P96 P101 = 55.4
  dimension "d304" distance P98 P102 = 50.4 (= "( 10 * 5 ) * 1 mm + 0.4 mm")
  dimension "d305" distance P98 P104 = 5
  dimension "d306" distance P102 P105 = 5
  dimension "d308" distance P104 P110 = 16.4
  dimension "d309" distance P110 P113 = 3.8 (= "d317")
  dimension "d316" distance P113 P116 = 18.4
  dimension "d317" distance P116 P119 = 3.8 (= "d319")
  dimension "d318" distance P119 P122 = 20.4
  dimension "d319" distance P122 P125 = 3.8 (= "d321")
  dimension "d320" distance P125 P128 = 22.4
  dimension "d321" distance P128 P131 = 3.8 (= "d323")
  dimension "d322" distance P131 P134 = 24.4
  dimension "d323" distance P134 P137 = 3.8 (= "d326")
  dimension "d324" distance P137 P140 = 26.4
  dimension "d325" distance P75 P143 = 28.4
  dimension "d326" distance = 3.8
  dimension "d334" distance P144 P145 = 12
  dimension "d335" distance P144 P147 = 120
  dimension "d336" distance = 65 (= "d337")
  dimension "d337" distance = 65
  dimension "d338" distance P148 P149 = 12
  dimension "d339" distance P148 P151 = 120
  dimension "d340" distance = 65 (= "d341")
  dimension "d341" distance = 65
  dimension "d342" = -3
  dimension "d343" = 3
  dimension "d401" distance P99 P160 = 10.4
  dimension "d402" distance P99 P162 = 15.4
  dimension "d403" distance P7 P163 = 14.4
  dimension "d404" distance P7 P165 = 21.4
  dimension "d405" distance P102 P168 = 5
  dimension "d406" distance P167 P169 = 16.4
  dimension "d407" distance P167 P171 = 24.4
  dimension "d408" distance P102 P172 = 20.4
  dimension "d409" distance P102 P174 = 30.4
  dimension "d410" distance P174 P177 = 5
  dimension "d411" distance P102 P180 = 5
  dimension "d416" distance P177 P181 = 5.4
  dimension "d417" distance P177 P183 = 15.4
  dimension "d418" distance P184 P185 = 6.4
  dimension "d419" distance P184 P187 = 18.4
  dimension "d420" distance P176 P188 = 7.4
  dimension "d421" distance P176 P190 = 21.4
  dimension "d422" distance = 7.9
  dimension "d423" distance = 4.55 (= "d424")
  dimension "d424" distance = 4.55
  dimension "d425" distance P191 P192 = 9.4
  dimension "d426" distance P191 P194 = 27.4
  dimension "d427" distance P195 P196 = 10.4
  dimension "d428" distance P195 P198 = 30.4
  dimension "d429" distance P199 P200 = 12.4
  dimension "d430" distance P199 P202 = 36.4
  dimension "d431" distance P6 P203 = 16.4
  dimension "d432" distance P6 P205 = 48.4
  dimension "d433" distance = 6.2 (= "d435")
  dimension "d434" distance = 6.2 (= "d433")
  dimension "d435" distance = 6.2
  dimension "d436" distance = 6.2 (= "d435")
  dimension "d487" distance P206 P207 = 11.4
  dimension "d488" distance P206 P209 = 16.9
  dimension "d489" distance = 6.05 (= "d490")
  dimension "d490" distance = 6.05
  dimension "d491" distance = 6
  dimension "d492" distance = 10.6
  dimension "d502" = -0.4
  dimension "d503" = 0.4
  dimension "d260" Text1-Height = 3
  dimension "d261" Text2-Height = 3
  dimension "d262" Text3-Height = 3
  dimension "d278" Text4-Height = 3
  dimension "d279" Text5-Height = 3
  dimension "d280" Text6-Height = 3
  dimension "d281" Text7-Height = 3
  dimension "d282" Text8-Height = 3
  dimension "d283" Text9-Height = 3
  dimension "d284" Text10-Height = 3
  dimension "d307" Text11-Height = 3
  dimension "d310" Text12-Height = 3
  dimension "d311" Text13-Height = 3
  dimension "d312" Text14-Height = 3
  dimension "d313" Text15-Height = 3
  dimension "d314" Text16-Height = 3
  dimension "d315" Text17-Height = 3
  dimension "d327" Text18-Height = 3
  dimension "d328" Text19-Height = 3
  dimension "d329" Text20-Height = 3
  dimension "d330" Text21-Height = 3
  dimension "d331" Text22-Height = 3
  dimension "d332" Text23-Height = 3
  dimension "d333" Text24-Height = 3
  dimension "d412" Text25-Height = 3
  dimension "d413" Text26-Height = 3
  dimension "d414" Text27-Height = 3
  dimension "d415" Text28-Height = 3
  dimension "d437" Text29-Height = 3
  dimension "d438" Text30-Height = 3
  dimension "d439" Text31-Height = 3
  dimension "d440" Text32-Height = 3
  dimension "d441" Text33-Height = 3
  dimension "d442" Text34-Height = 3
  dimension "d443" Text35-Height = 3
  dimension "d493" Text36-Height = 3
sketch "Sketch6" plane through (0, 0, 0) normal (0, 0, 1) x axis (1, 0, 0)
  line L1 (684.5, 75) -> (500, 75)
  line L2 (684.5, -175) -> (684.5, 75)
  line L3 (500, -175) -> (684.5, -175)
  line L4 (500, 75) -> (500, -175)
  point P2 (500, 75)
  point P3 (684.5, 75)
  point P5 (500, -175)
  horizontal L1
  vertical L2
  horizontal L3
  vertical L4
  dimension "d344" distance P2 P3 = 184.5
  dimension "d345" distance P2 P5 = 250
extrude "Extrude10" new body sketch "Sketch6" along normal blind 5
